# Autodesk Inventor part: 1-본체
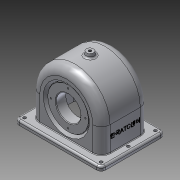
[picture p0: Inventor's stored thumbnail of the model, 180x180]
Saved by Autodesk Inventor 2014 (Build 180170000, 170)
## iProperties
Created: 2015-09
Part Number: 1-본체
Material: 알루미늄 6061
Document SubType Name: Modeling
Designer: Administrator
Density: 2.71 g/cm^3
Appearance: 알루미늄 - 평지
Mass: 809.5 g
Surface Area: 878.329 cm^2
Volume: 298.708 cm^3
Author: Administrator
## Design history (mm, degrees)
sketch "스케치1"
  geometry: L1 (57, 0)-(57, -47); L2 (57, -47)-(-57, -47); L3 (-57, -47)-(-57, 0); L4 (57, 0)-(-57, 0); A1 r 57 centre (0, 0) between (57, 0) and (-57, 0); 1 further point
  constraints: 8 end point, 2 perpendicular, 2 point on circle, 2 tangent, 1 centre point, 1 coincident, 1 vertical
  dimensions: "d3" = 57 radius of A1; "d4" = 104 dimension on A1 L2
extrude "돌출1" new body sketch "스케치1" distance "d5" = 77; taper "d6" = 0 deg
sketch "스케치2"
  geometry: L1 (-13, -13.5)-(127, -13.5); L2 (127, -13.5)-(127, 90.5); L3 (127, 90.5)-(-13, 90.5); L4 (-13, 90.5)-(-13, -13.5); L5 (0, 0)-(0, 77) reference; L6 (114, 0)-(0, 0) reference; 5 further points
  constraints: 8 end point, 4 midpoint, 2 parallel, 1 horizontal, 1 horizontal alignment, 1 perpendicular, 1 vertical alignment
  dimensions: "d7" = 140 distance of L2.end L3.end; "d8" = 104 distance of L3.end L1.start
extrude "돌출2" join sketch "스케치2" distance "d9" = 7; taper "d10" = 0 deg
fillet "모깎기1" dims "d11" = 14
feature "쉘1" dims "d12" = 5, "d103" = 7
sketch "스케치3"
  geometry: C1 r 31 at (0, 0); 1 further point
  constraints: 1 centre point, 1 coincident
  dimensions: "d13" = 62 diameter of C1
extrude "돌출3" join sketch "스케치3" distance "d14" = 10; taper "d15" = 0 deg
sketch "스케치4"
  geometry: L1 (5, 39.747)-(19, 28); L2 (19, 28)-(19, 0); L3 (19, 0)-(5, 0); L4 (5, 0)-(5, 39.747); L5 (5, 0)-(5, 43) reference; 1 further point
  constraints: 8 end point, 2 perpendicular, 1 collinear, 1 point on line, 1 vertical
  dimensions: "d16" = 28 distance of L1.end L2.end; "d17" = 50 deg angle of L2 L1; "d18" = 14 distance of L2.end L3.end
revolve "회전1" sketch "스케치4" stored, may be unused: angle "d19" = 90 deg
sketch "스케치7"
  geometry: L1 (5, 39.747)-(19, 28) reference; L2 (0, 37.416)-(5.263, 33); L3 (0, 0)-(0, 43) reference; L4 (3, 0)-(3, 33); L5 (3, 33)-(5.263, 33); L6 (3, 0)-(0, 0)
  constraints: 8 end point, 2 parallel, 1 horizontal, 1 perpendicular, 1 point on line
  dimensions: "d21" = 5 distance between parallel lines of L2 L1; "d22" = 3 distance between parallel lines of L4 L3; "d23" = 33 distance of L4.start L4.end
revolve "회전2" sketch "스케치7" stored, may be unused: angle "d25" = 90 deg
hole "구멍1" diameter "d28" = 40; stored, may be unused: countersink angle "d32" = 90 deg, drill point angle "d34" = 0 deg; dims "d26" = 10, "d27" = 10, "d29" = 6, "d30" = 4, "d31" = 2, "d33" = 8
node "작업 평면1"
sketch "스케치8"
  geometry: L1 (140, 104)-(140, 0) reference; L2 (0, 104)-(140, 104) reference; C1 r 6 at (70, 52); 2 further points
  constraints: 1 centre point, 1 horizontal alignment, 1 midpoint, 1 vertical alignment
  dimensions: "d37" = 12 diameter of C1
extrude "돌출4" join sketch "스케치8" stored distance "d38" = 5; taper "d39" = 10 deg
fillet "모깎기2" dims "d40" = 7
fillet "모깎기3" dims "d41" = 3
sketch "스케치9"
  geometry: L1 (0, 0)-(0, 28)
  constraints: 2 end point, 1 vertical
  dimensions: "d42" = 28 distance of L1.start L1.end
hole "구멍2" sketch "스케치9" at (0, 28) diameter "d43" = 2.459; stored, may be unused: countersink angle "d47" = 90 deg, drill point angle "d49" = 118 deg; dims "d44" = 7, "d45" = 4, "d46" = 2, "d48" = 9
sketch "스케치10"
  geometry: L1 (0, 0)-(0, -24)
  constraints: 2 end point, 1 vertical
  dimensions: "d53" = 24 distance of L1.start L1.end
hole "구멍3" sketch "스케치10" at (0, -24) diameter "d54" = 2.459; stored, may be unused: countersink angle "d58" = 90 deg, drill point angle "d60" = 118 deg; dims "d55" = 6, "d56" = 4, "d57" = 2, "d59" = 8
hole "구멍4" diameter "d66" = 4.459; stored, may be unused: countersink angle "d70" = 90 deg, drill point angle "d72" = 118 deg; dims "d67" = 20, "d68" = 4, "d69" = 2, "d71" = 8, "d73" = 10, "d74" = 10
fillet "모깎기4" dims "d75" = 0.5
fillet "모깎기5" dims "d76" = 1
fillet "모깎기6" dims "d77" = 3
chamfer "모따기1" distance "d78" = 1; stored, may be unused: second distance "d79" = 2, angle "d80" = 45 deg
sketch "스케치13"
  geometry: L1 (126, -99)-(-2, -99) reference; L2 (126, -5)-(126, -99) reference; L3 (-2, -99)-(-2, -5) reference; L4 (-2, -5)-(126, -5) reference; L5 (20, -18.5)-(106, -18.5) reference; L6 (115, -27.5)-(115, -76.5) reference; L7 (106, -85.5)-(20, -85.5) reference; L8 (11, -76.5)-(11, -27.5) reference; A1 r 9 centre (106, -27.5) between (115, -27.5) and (106, -18.5) reference; A2 r 9 centre (106, -76.5) between (106, -85.5) and (115, -76.5) reference; A3 r 9 centre (20, -76.5) between (11, -76.5) and (20, -85.5) reference; A4 r 9 centre (20, -27.5) between (20, -18.5) and (11, -27.5) reference; 1 further point
extrude "돌출5" join sketch "스케치13" distance "d104" = 5; taper "d105" = 0 deg
sketch "스케치11"
  geometry: L1 (-119, 82.5)-(5, 82.5); L2 (5, 82.5)-(5, -5.5); L3 (5, -5.5)-(-119, -5.5); L4 (-119, -5.5)-(-119, 82.5); L5 (-127, 83.5)-(-127, -6.5) reference; L6 (6, 90.5)-(-120, 90.5) reference; 3 further points
  constraints: 8 end point, 2 midpoint, 2 parallel, 1 horizontal, 1 perpendicular
  dimensions: "d81" = 124 distance of L1.start L1.end; "d82" = 88 distance of L1.end L2.end; "d83" = 8 distance between parallel lines of L4 L5; "d84" = 8 distance between parallel lines of L6 L1; "d102" = 44 distance of L2.end point (5, 38.5) (derived)
hole "구멍5" sketch "스케치11" at (5, -5.5) diameter "d85" = 5; stored, may be unused: countersink angle "d89" = 90 deg, drill point angle "d91" = 0 deg; dims "d86" = 6, "d87" = 4, "d88" = 2, "d90" = 8
sketch "스케치12"
  geometry: L1 (13.398, 22.271)-(13.398, 26.729); L2 (13.398, 26.729)-(20.602, 26.729); L3 (20.602, 26.729)-(20.602, 22.271); L4 (20.602, 22.271)-(13.398, 22.271); L5 (47, 69.5)-(47, -20.5) reference; L6 (43, -20.5)-(43, 69.5) reference; L7 (40, 69.5)-(40, -20.5) reference; 4 further points
  constraints: 3 midpoint, 1 horizontal alignment, 2 other
  dimensions: "d99" = 30 distance from line of L5 point (17, 26.729)
feature "엠보싱1" sketch "스케치12" dims "d3" = 57, "d4" = 104, "d11" = 14, "d100" = 0.5, "d101" = 0
node "솔리드1"
pattern_circular "원형 패턴1" dims angle "d51" = 360 deg
pattern_circular "원형 패턴2" dims angle "d62" = 360 deg
pattern_linear "직사각형 패턴1" dims "d94" = 44 (= d102), "d97" = 124 (= d81)
other parameters: "d1" = 57, "d2" = 104, "d98" = 62 (derived)
